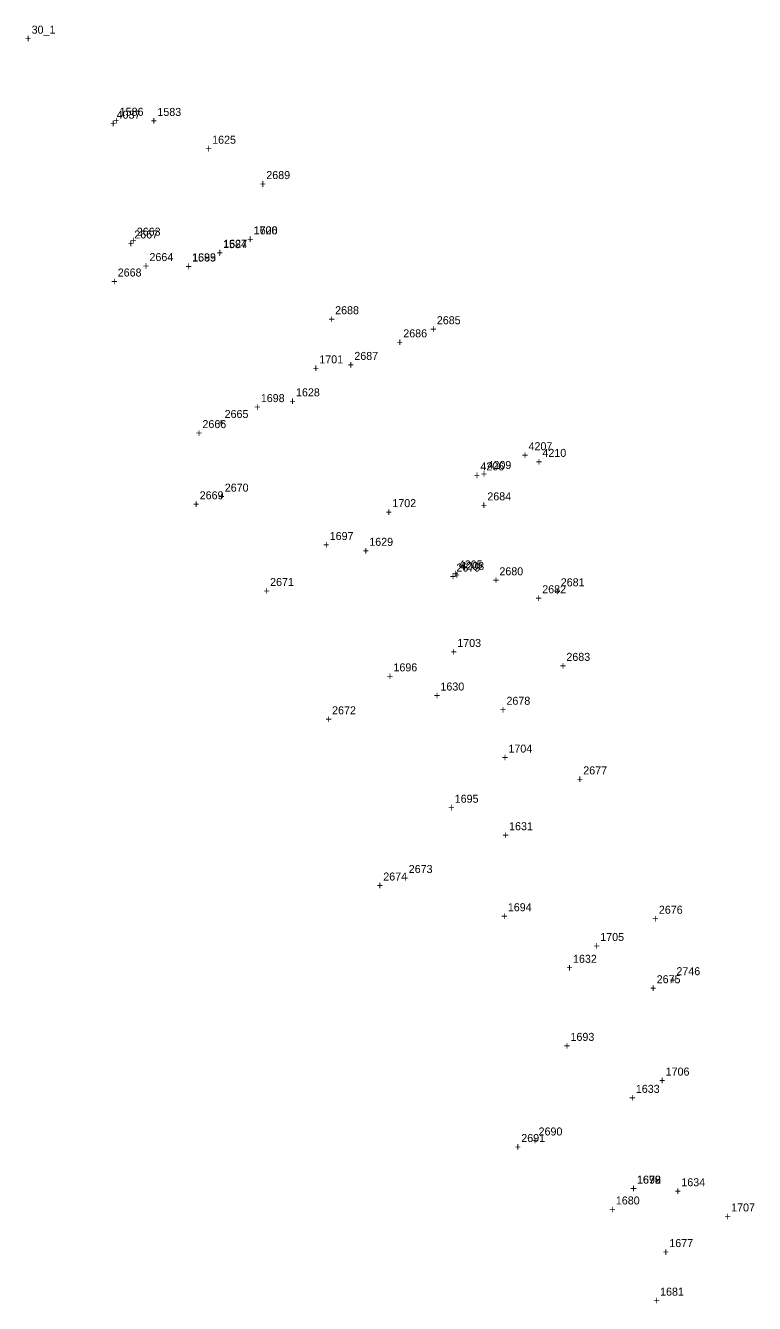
# Model space of a CAD drawing. Extents: x 1036751 to 1042192, y 772604 to 785439.
# Drawn here: x 1039326.7 to 1039554.3, y 776607 to 777006.3 of the extents above; entities that cross this region are included whole.
import ezdxf

# ---------------------------------------------------------------- set-up
doc = ezdxf.new("R2010")
doc.units = 0
for name, color, linetype in [('S_Buildings', 7, 'Continuous'), ('S_Control_Geodetic_ControlPoint', 7, 'Continuous'), ('S_Fencing_ChainLink', 7, 'Continuous'), ('S_Ground_LevelString', 7, 'Continuous'), ('S_Property_IronPipeFound', 7, 'Continuous'), ('S_Property_Mailbox', 7, 'Continuous'), ('S_Roadway_Centerline', 7, 'Continuous'), ('S_Roadway_Edge_Pavement', 7, 'Continuous'), ('S_Traffic_Sign_DoublePost', 7, 'Continuous'), ('S_Traffic_Sign_SinglePost', 7, 'Continuous'), ('S_Trees_Decid_NonPay', 7, 'Continuous'), ('S_Trees_Decid_Pay', 7, 'Continuous'), ('S_Utilities_GuyWire3', 7, 'Continuous'), ('S_Utilities_Pole_Power', 7, 'Continuous'), ('S_Utilities_Pole_Support3', 7, 'Continuous'), ('S_Utilities_UG_Electrical_Line', 7, 'Continuous'), ('S_Utilities_UG_OilLine', 7, 'Continuous'), ('S_Utilities_UG_Water_Line', 7, 'Continuous')]:
    doc.layers.add(name, color=color, linetype=linetype)

msp = doc.modelspace()

# ---------------------------------------------------------------- texts
at = {"layer": 'S_Buildings'}
for s, p in [('2681', (1039493.81, 776831.07)), ('2682', (1039488.03, 776828.89)), ('+', (1039491.75, 776828.32)), ('+', (1039485.97, 776826.14)), ('2683', (1039495.57, 776807.77)), ('+', (1039493.51, 776805.02))]:
    msp.add_text(s, height=2.5, dxfattribs=at).set_placement(p)
at = {"layer": 'S_Control_Geodetic_ControlPoint'}
for s, p in [('30', (1039328.58, 777003.75)), ('30', (1039328.58, 777003.75)), ('30', (1039328.58, 777003.75)), ('30', (1039328.58, 777003.75)), ('30', (1039328.58, 777003.75)), ('30', (1039328.58, 777003.75)), ('30', (1039328.58, 777003.75)), ('30', (1039328.58, 777003.75)), ('30', (1039328.58, 777003.75)), ('30', (1039328.58, 777003.75)), ('30_1', (1039328.58, 777003.75)), ('+', (1039326.52, 777001)), ('+', (1039326.52, 777001)), ('+', (1039326.52, 777001)), ('+', (1039326.52, 777001)), ('+', (1039326.52, 777001)), ('+', (1039326.52, 777001)), ('+', (1039326.52, 777001)), ('+', (1039326.52, 777001)), ('+', (1039326.52, 777001)), ('+', (1039326.52, 777001)), ('+', (1039326.52, 777001))]:
    msp.add_text(s, height=2.5, dxfattribs=at).set_placement(p)
at = {"layer": 'S_Fencing_ChainLink'}
for s, p in [('2670', (1039388.89, 776860.65)), ('+', (1039379, 776855.51)), ('2669', (1039381.06, 776858.26)), ('+', (1039386.83, 776857.9)), ('2671', (1039403.05, 776831.16)), ('+', (1039400.99, 776828.41)), ('2672', (1039422.4, 776791.07)), ('+', (1039420.33, 776788.32)), ('2674', (1039438.39, 776739.13)), ('2673', (1039446.34, 776741.48)), ('+', (1039436.33, 776736.38)), ('+', (1039444.28, 776738.73))]:
    msp.add_text(s, height=2.5, dxfattribs=at).set_placement(p)
at = {"layer": 'S_Ground_LevelString'}
for s, p in [('1678', (1039517.65, 776644.42)), ('+', (1039515.59, 776641.67)), ('1677', (1039527.72, 776624.59)), ('+', (1039525.66, 776621.84))]:
    msp.add_text(s, height=2.5, dxfattribs=at).set_placement(p)
at = {"layer": 'S_Property_IronPipeFound'}
for s, p in [('2677', (1039500.84, 776772.3)), ('+', (1039498.78, 776769.55))]:
    msp.add_text(s, height=2.5, dxfattribs=at).set_placement(p)
at = {"layer": 'S_Property_Mailbox'}
for s, p in [('+', (1039474.79, 776791.3)), ('2678', (1039476.85, 776794.05))]:
    msp.add_text(s, height=2.5, dxfattribs=at).set_placement(p)
at = {"layer": 'S_Roadway_Centerline'}
for s, p in [('+', (1039365.78, 776975.3)), ('1583', (1039367.85, 776978.05)), ('1584', (1039388.36, 776936.74)), ('1627', (1039388.43, 776936.88)), ('+', (1039386.3, 776933.99)), ('+', (1039386.37, 776934.13)), ('1628', (1039411.14, 776890.43)), ('+', (1039409.08, 776887.68)), ('1629', (1039434.02, 776843.72)), ('+', (1039431.96, 776840.97)), ('+', (1039454.18, 776795.75)), ('1630', (1039456.24, 776798.5)), ('1631', (1039477.67, 776754.85)), ('+', (1039475.61, 776752.1)), ('1632', (1039497.64, 776713.42)), ('+', (1039495.58, 776710.67)), ('1633', (1039517.26, 776672.79)), ('+', (1039515.2, 776670.04)), ('1634', (1039531.47, 776643.6)), ('+', (1039529.41, 776640.85))]:
    msp.add_text(s, height=2.5, dxfattribs=at).set_placement(p)
at = {"layer": 'S_Roadway_Edge_Pavement'}
for s, p in [('+', (1039354.02, 776975.35)), ('1586', (1039356.08, 776978.1)), ('1625', (1039384.95, 776969.36)), ('+', (1039382.89, 776966.61)), ('1700', (1039397.9, 776941.05)), ('1626', (1039397.95, 776941.04)), ('+', (1039395.84, 776938.3)), ('+', (1039395.88, 776938.29)), ('1699', (1039378.7, 776932.61)), ('1585', (1039378.72, 776932.56)), ('+', (1039376.64, 776929.86)), ('+', (1039376.66, 776929.81)), ('1701', (1039418.42, 776900.73)), ('+', (1039416.36, 776897.98)), ('1698', (1039400.15, 776888.62)), ('+', (1039398.09, 776885.87)), ('1702', (1039441.22, 776855.8)), ('+', (1039439.16, 776853.05)), ('1697', (1039421.66, 776845.54)), ('+', (1039419.6, 776842.8)), ('1703', (1039461.49, 776812.11)), ('+', (1039459.43, 776809.36)), ('1696', (1039441.57, 776804.49)), ('+', (1039439.51, 776801.74)), ('1704', (1039477.47, 776779.11)), ('+', (1039475.41, 776776.36)), ('1695', (1039460.7, 776763.44)), ('+', (1039458.64, 776760.69)), ('1694', (1039477.28, 776729.54)), ('+', (1039475.22, 776726.79)), ('1705', (1039506.14, 776720.23)), ('+', (1039504.08, 776717.48)), ('1693', (1039496.86, 776689.04)), ('+', (1039494.8, 776686.29)), ('+', (1039524.51, 776675.43)), ('1706', (1039526.57, 776678.18)), ('1679', (1039517.59, 776644.42)), ('1692', (1039517.66, 776644.41)), ('+', (1039515.53, 776641.67)), ('+', (1039515.6, 776641.66)), ('1680', (1039511.02, 776637.91)), ('1707', (1039547.02, 776635.72)), ('+', (1039508.96, 776635.16)), ('+', (1039544.96, 776632.97)), ('1681', (1039524.83, 776609.41)), ('+', (1039522.77, 776606.66))]:
    msp.add_text(s, height=2.5, dxfattribs=at).set_placement(p)
at = {"layer": 'S_Traffic_Sign_DoublePost'}
for s, p in [('2685', (1039455.11, 776912.96)), ('2686', (1039444.64, 776908.86)), ('+', (1039453.04, 776910.21)), ('+', (1039442.58, 776906.11)), ('2690', (1039486.89, 776659.47)), ('2691', (1039481.48, 776657.42)), ('+', (1039484.83, 776656.72)), ('+', (1039479.42, 776654.67))]:
    msp.add_text(s, height=2.5, dxfattribs=at).set_placement(p)
at = {"layer": 'S_Traffic_Sign_SinglePost'}
for s, p in [('2676', (1039524.45, 776728.75)), ('+', (1039522.38, 776726))]:
    msp.add_text(s, height=2.5, dxfattribs=at).set_placement(p)
at = {"layer": 'S_Trees_Decid_NonPay'}
for s, p in [('2680', (1039474.65, 776834.51)), ('+', (1039472.59, 776831.76))]:
    msp.add_text(s, height=2.5, dxfattribs=at).set_placement(p)
at = {"layer": 'S_Trees_Decid_Pay'}
for s, p in [('+', (1039468.82, 776855.17)), ('2684', (1039470.88, 776857.92)), ('2746', (1039529.93, 776709.55)), ('+', (1039527.87, 776706.8))]:
    msp.add_text(s, height=2.5, dxfattribs=at).set_placement(p)
at = {"layer": 'S_Utilities_GuyWire3'}
for s, p in [('2664', (1039365.38, 776932.7)), ('+', (1039363.32, 776929.95)), ('2688', (1039423.36, 776916.09)), ('+', (1039421.29, 776913.34)), ('2666', (1039381.91, 776880.5)), ('+', (1039379.85, 776877.75))]:
    msp.add_text(s, height=2.5, dxfattribs=at).set_placement(p)
at = {"layer": 'S_Utilities_Pole_Power'}
for s, p in [('2689', (1039401.86, 776958.32)), ('+', (1039399.8, 776955.57)), ('2663', (1039361.4, 776940.62)), ('+', (1039359.34, 776937.87)), ('+', (1039427.29, 776899.06)), ('2687', (1039429.35, 776901.81)), ('2679', (1039461.23, 776835.68)), ('+', (1039459.17, 776832.93)), ('2675', (1039523.77, 776707.04)), ('+', (1039521.71, 776704.29))]:
    msp.add_text(s, height=2.5, dxfattribs=at).set_placement(p)
at = {"layer": 'S_Utilities_Pole_Support3'}
for s, p in [('2665', (1039388.84, 776883.67)), ('+', (1039386.78, 776880.92))]:
    msp.add_text(s, height=2.5, dxfattribs=at).set_placement(p)
at = {"layer": 'S_Utilities_UG_Electrical_Line'}
for s, p in [('2667', (1039360.64, 776939.76)), ('+', (1039358.57, 776937.01)), ('2668', (1039355.46, 776927.87)), ('+', (1039353.4, 776925.12)), ('+', (1039481.69, 776870.84)), ('4207', (1039483.75, 776873.59)), ('4206', (1039468.71, 776867.29)), ('+', (1039466.65, 776864.54)), ('4205', (1039461.98, 776836.65)), ('+', (1039459.92, 776833.9))]:
    msp.add_text(s, height=2.5, dxfattribs=at).set_placement(p)
at = {"layer": 'S_Utilities_UG_OilLine'}
for s, p in [('4210', (1039488.09, 776871.51)), ('4209', (1039470.93, 776867.72)), ('+', (1039486.03, 776868.76)), ('+', (1039468.87, 776864.97)), ('4208', (1039462.43, 776836.15)), ('+', (1039460.37, 776833.4))]:
    msp.add_text(s, height=2.5, dxfattribs=at).set_placement(p)
at = {"layer": 'S_Utilities_UG_Water_Line'}
for s, p in [('4037', (1039355.13, 776977.18)), ('+', (1039353.07, 776974.43))]:
    msp.add_text(s, height=2.5, dxfattribs=at).set_placement(p)

doc.saveas('drawing.dxf')
